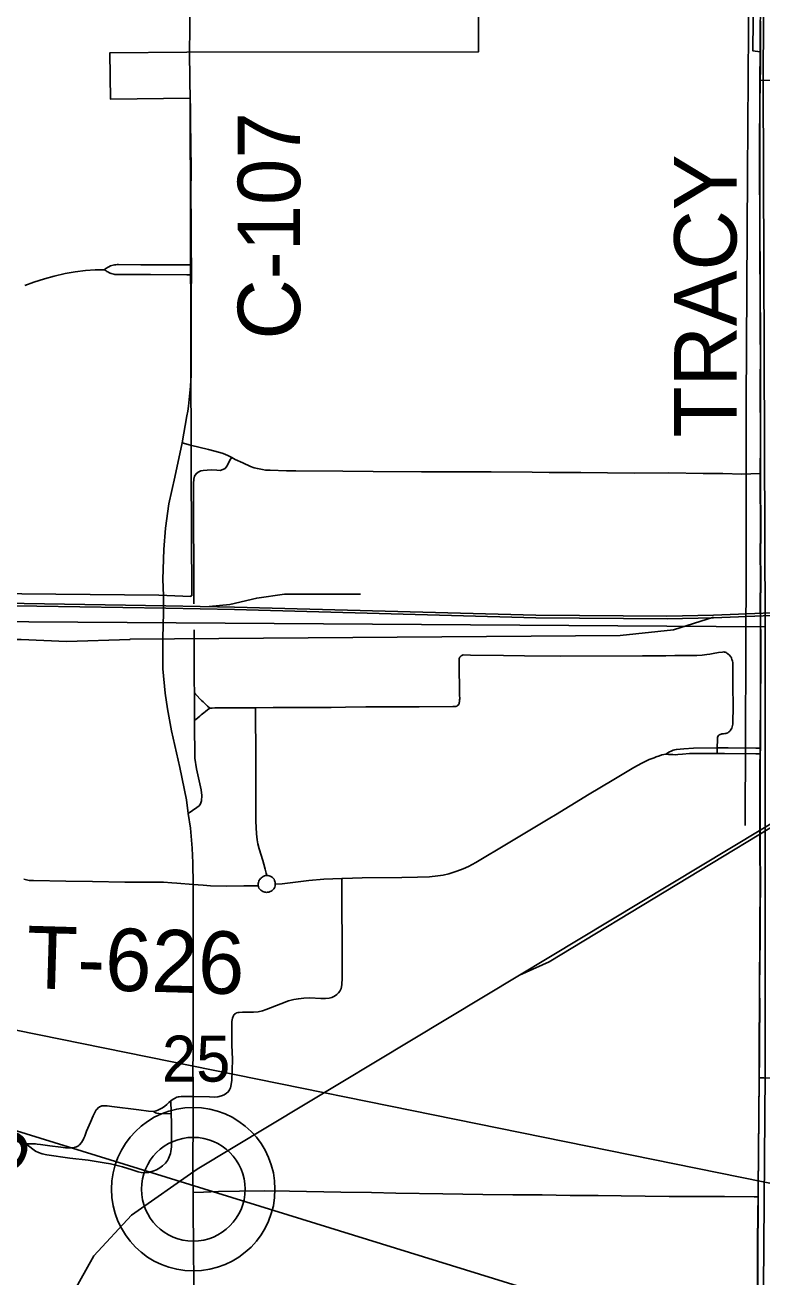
# Model space of a CAD drawing. Extents: x 0 to 34, y 0 to 22.
# Drawn here: x 7.896 to 8.567, y 19.262 to 20.401 of the extents above; entities that cross this region are included whole.
import ezdxf

# ---------------------------------------------------------------- set-up
doc = ezdxf.new("R2010")
doc.units = 0
for name, color, linetype in [('GM_X_City_Street', 7, 'Continuous'), ('GM_X_Corporation', 7, 'Continuous'), ('GM_X_County_Road', 7, 'Continuous'), ('GM_X_County_Road_Text', 7, 'Continuous'), ('GM_X_Minor_River', 7, 'Continuous'), ('GM_X_Rail_Line', 7, 'Continuous'), ('GM_X_Section_Text', 7, 'Continuous'), ('GM_X_Township_Road', 7, 'Continuous'), ('GM_X_Township_Road_Text', 7, 'Continuous'), ('GM_X_Unincorporated', 7, 'Continuous'), ('GM_X_Unincorporated_Location', 7, 'Continuous'), ('SH_Text', 7, 'Continuous')]:
    doc.layers.add(name, color=color, linetype=linetype)

msp = doc.modelspace()

# ---------------------------------------------------------------- linework, layer by layer
at = {"layer": 'GM_X_City_Street'}
for points in [[(7.8957, 20.1645), (7.9039, 20.1675), (7.9134, 20.1706), (7.9224, 20.173), (7.9322, 20.1752), (7.9415, 20.1768), (7.9508, 20.1779), (7.9595, 20.1785), (7.9632, 20.1787), (7.9677, 20.1787)], [(7.9677, 20.1787), (7.9687, 20.1795), (7.9698, 20.1802), (7.9709, 20.1808), (7.9721, 20.1815), (7.9735, 20.1823), (7.9749, 20.1827), (7.9761, 20.183), (7.9772, 20.1832), (7.9783, 20.1833), (7.9795, 20.1834), (7.9809, 20.1834), (8.0012, 20.1833), (8.0229, 20.1833), (8.0392, 20.1833), (8.0428, 20.1833), (8.0472, 20.1833)], [(7.9677, 20.1787), (7.9687, 20.1782), (7.9695, 20.1777), (7.9702, 20.1772), (7.9712, 20.1767), (7.9721, 20.1763), (7.9732, 20.1757), (7.9742, 20.1754), (7.9754, 20.175), (7.9765, 20.1747), (7.9774, 20.1745), (7.9785, 20.1744), (7.9799, 20.1744), (7.9997, 20.1743), (8.0101, 20.1743), (8.0429, 20.1742), (8.0472, 20.1742)]]:
    msp.add_lwpolyline(points, dxfattribs=at)
at = {"layer": 'GM_X_Corporation'}
for points in [[(7.7961, 20.8998), (8.0431, 20.8969), (8.5706, 20.8869), (8.5677, 20.3491), (8.5695, 19.8537), (7.5413, 19.8609), (7.5417, 20.3812), (7.5405, 20.8943)], [(7.5413, 19.8609), (8.5695, 19.8537), (8.5696, 19.4474), (8.5646, 18.8232), (7.5285, 18.8343)]]:
    msp.add_lwpolyline(points, close=True, dxfattribs=at)
for points in [[(8.5605, 20.5722), (8.5584, 20.3778), (8.565, 20.3771), (8.5647, 20.351), (8.9, 20.3511), (8.9, 20.9)], [(7.3931, 19.8888), (8.0175, 19.8825), (8.0468, 19.8814), (8.0468, 19.8821), (8.0475, 19.8821), (8.0471, 19.9967), (8.046, 20.335), (7.9734, 20.3341), (7.9728, 20.376), (8.043, 20.3766), (8.3087, 20.3771), (8.3095, 20.5721)], [(8.5654, 20.4308), (8.565, 20.3824), (8.565, 20.3625), (8.5647, 20.351), (8.5646, 20.3286), (8.5645, 20.2956), (8.5644, 20.2608), (8.5646, 20.2322), (8.5646, 20.2049), (8.5647, 20.1874), (8.5649, 20.1613), (8.5651, 20.1197), (8.5652, 20.1012), (8.5651, 20.0757), (8.5652, 20.0216), (8.5651, 19.9937), (8.5651, 19.9924), (8.5652, 19.9383), (8.565, 19.9215), (8.5653, 19.8985), (8.5651, 19.8718), (8.5652, 19.8606), (8.5653, 19.8435), (8.5654, 19.8267), (8.5652, 19.7782), (8.5651, 19.7596), (8.5649, 19.744), (8.5649, 19.7388), (8.5647, 19.7279), (8.5648, 19.6949), (8.5647, 19.6769), (8.5646, 19.6657), (8.5647, 19.6564), (8.5648, 19.6458), (8.565, 19.6272), (8.5647, 19.5712), (8.5643, 19.5264), (8.5644, 19.5071), (8.5642, 19.481), (8.5641, 19.4624), (8.564, 19.4439), (8.5631, 19.3418), (8.5631, 19.3356), (8.5629, 19.3194), (8.5627, 19.2945), (8.5626, 19.2541)], [(8.5626, 19.2541), (8.5627, 19.2945), (8.5629, 19.3194), (8.5631, 19.3356), (8.5631, 19.3418), (8.564, 19.4439), (8.5641, 19.4624), (8.5642, 19.481), (8.5644, 19.5071), (8.5643, 19.5264), (8.5647, 19.5712), (8.565, 19.6272), (8.5648, 19.6458), (8.5647, 19.6564), (8.5646, 19.6657), (8.5647, 19.6769), (8.5648, 19.6949), (8.5647, 19.7279), (8.5649, 19.7388), (8.5649, 19.744), (8.5651, 19.7596), (8.5652, 19.7782), (8.5654, 19.8267), (8.5653, 19.8435), (8.5652, 19.8606), (8.5651, 19.8718), (8.5653, 19.8985), (8.565, 19.9215), (8.5652, 19.9383), (8.5651, 19.9924), (8.5651, 19.9937), (8.5652, 20.0216), (8.5651, 20.0757), (8.5652, 20.1012), (8.5651, 20.1197), (8.5649, 20.1613), (8.5647, 20.1874), (8.5646, 20.2049), (8.5646, 20.2322), (8.5644, 20.2608), (8.5645, 20.2956), (8.5646, 20.3286), (8.5647, 20.351), (8.565, 20.3625), (8.565, 20.3824), (8.5654, 20.4308)]]:
    msp.add_lwpolyline(points, dxfattribs=at)
at = {"layer": 'GM_X_County_Road'}
for p, q in [((8.0462, 20.3316), (8.0454, 20.3754)), ((8.0472, 20.1742), (8.0472, 20.1833))]:
    msp.add_line(p, q, dxfattribs=at)
for points in [[(8.0454, 20.3754), (8.0458, 20.3992), (8.046, 20.4477), (8.046, 20.4825), (8.0463, 20.5398), (8.0465, 20.5935), (8.0465, 20.6202), (8.0465, 20.6273), (8.0467, 20.6395)], [(8.5649, 20.3505), (8.5652, 20.3619), (8.5652, 20.3818), (8.5654, 20.405)], [(8.5653, 19.9932), (8.5654, 20.021), (8.5653, 20.0751), (8.5654, 20.1006), (8.5653, 20.1191), (8.5651, 20.1608), (8.5649, 20.1869), (8.5648, 20.2043), (8.5648, 20.2317), (8.5647, 20.2603), (8.5648, 20.2951), (8.5648, 20.328), (8.5649, 20.3505)], [(8.0472, 20.1833), (8.0472, 20.1857), (8.047, 20.1938), (8.047, 20.2204), (8.0468, 20.2484), (8.0469, 20.2702), (8.0464, 20.3137), (8.0463, 20.3288), (8.0462, 20.3316)], [(8.0463, 20.0729), (8.0471, 20.0829), (8.0469, 20.0995), (8.0471, 20.1156), (8.0471, 20.1579), (8.0472, 20.1742)], [(8.0388, 20.0211), (8.0431, 20.0457), (8.0439, 20.05), (8.0446, 20.0547), (8.0452, 20.0605), (8.0463, 20.0729)], [(8.0217, 19.8821), (8.0213, 19.8973), (8.022, 19.9243), (8.0236, 19.9437), (8.0268, 19.9656), (8.0321, 19.9899), (8.0388, 20.0211)], [(8.5651, 19.7383), (8.5652, 19.7435), (8.5653, 19.759), (8.5654, 19.7777), (8.5656, 19.8262), (8.5655, 19.843), (8.5654, 19.86), (8.5653, 19.8712), (8.5655, 19.8979), (8.5652, 19.921), (8.5655, 19.9377), (8.5653, 19.9918), (8.5653, 19.9932)], [(8.0444, 19.6839), (8.0426, 19.6963), (8.0366, 19.7258), (8.029, 19.759), (8.0255, 19.7791), (8.0232, 19.7934), (8.0213, 19.8157), (8.0211, 19.8436), (8.0218, 19.8669), (8.0218, 19.8812), (8.0217, 19.8821)], [(8.565, 19.5876), (8.5652, 19.6266), (8.565, 19.6453), (8.5649, 19.6558), (8.5649, 19.6651), (8.565, 19.6763), (8.5651, 19.6944), (8.565, 19.7273), (8.5651, 19.7383)], [(8.0487, 19.6194), (8.0486, 19.6391), (8.0479, 19.6525), (8.0463, 19.6705), (8.0444, 19.6839)], [(8.0488, 19.4265), (8.0488, 19.4301), (8.0487, 19.4381), (8.0486, 19.4504), (8.0487, 19.4663), (8.0488, 19.4878), (8.0488, 19.4895), (8.0488, 19.4953), (8.0488, 19.5278), (8.0488, 19.552), (8.0488, 19.5788), (8.0487, 19.6194)], [(8.5644, 19.4775), (8.5644, 19.4805), (8.5646, 19.5066), (8.5645, 19.5259), (8.5649, 19.5706), (8.565, 19.5876)], [(8.5642, 19.4433), (8.5644, 19.4618), (8.5644, 19.4775)], [(8.5633, 19.335), (8.5633, 19.3412), (8.5642, 19.4433)], [(8.0487, 19.339), (8.0485, 19.3518), (8.0488, 19.4183), (8.0488, 19.4265)], [(8.0487, 19.0766), (8.0487, 19.0828), (8.0489, 19.105), (8.0488, 19.2026), (8.049, 19.2263), (8.0489, 19.2288), (8.0492, 19.2405), (8.0493, 19.2573), (8.049, 19.2883), (8.0488, 19.325), (8.0487, 19.3306), (8.0487, 19.339)], [(8.5621, 19.1128), (8.5618, 19.1454), (8.562, 19.1901), (8.5625, 19.22), (8.5628, 19.2536), (8.5629, 19.294), (8.5631, 19.3188), (8.5633, 19.335)]]:
    msp.add_lwpolyline(points, dxfattribs=at)
at = {"layer": 'GM_X_Minor_River'}
msp.add_lwpolyline([(8.5556, 20.857), (8.5541, 20.7765), (8.554, 20.6532), (8.5547, 20.441), (8.5535, 20.2661), (8.5523, 20.057), (8.5522, 19.9109), (8.5514, 19.673)], dxfattribs=at)
at = {"layer": 'GM_X_Rail_Line'}
for points in [[(6.9125, 19.8919), (7.7104, 19.8779), (8.0238, 19.873), (8.0864, 19.8717), (8.3608, 19.8644), (8.4801, 19.8635), (8.5225, 19.8644), (8.5752, 19.8664), (8.6397, 19.8712), (8.6895, 19.8758), (8.7741, 19.8862), (8.8479, 19.894), (8.8982, 19.8986), (8.9, 19.8988)], [(6.9125, 19.8896), (7.7104, 19.8755), (8.0238, 19.8707), (8.0863, 19.8694), (8.3608, 19.862), (8.4802, 19.8611), (8.5226, 19.862), (8.5753, 19.8641), (8.6399, 19.8689), (8.6898, 19.8735), (8.7744, 19.8839), (8.8481, 19.8917), (8.8984, 19.8963), (8.9, 19.8965)], [(8.3458, 19.5368), (8.6204, 19.7022), (8.6886, 19.7422), (8.7029, 19.7509), (8.7177, 19.7607), (8.7265, 19.7674), (8.735, 19.7742), (8.7726, 19.8102), (8.7996, 19.8361), (8.811, 19.8463), (8.8251, 19.8577), (8.8403, 19.8675), (8.8538, 19.8752), (8.8697, 19.8821), (8.8909, 19.8894), (8.9, 19.8916)], [(8.0633, 19.8722), (8.0823, 19.8741), (8.1067, 19.88), (8.1319, 19.8835), (8.2012, 19.8835)], [(7.9911, 19.8427), (8.4375, 19.8458), (8.4861, 19.8511), (8.5224, 19.8626)], [(7.1918, 18.2168), (7.1976, 18.2415), (7.1985, 18.2668), (7.1971, 18.288), (7.1907, 18.3043), (7.1721, 18.3357), (7.1648, 18.3522), (7.1593, 18.374), (7.1584, 18.3906), (7.1596, 18.4069), (7.163, 18.42), (7.1898, 18.4877), (7.3035, 18.7703), (7.7161, 19.7423), (7.7367, 19.7856), (7.7522, 19.8033), (7.7707, 19.8183), (7.7881, 19.8278), (7.8054, 19.8353), (7.8226, 19.8392), (7.8515, 19.8421), (7.8923, 19.8423), (7.9335, 19.8404), (7.9913, 19.8421)], [(8.3458, 19.5368), (8.3728, 19.5489), (8.6055, 19.6898), (8.6362, 19.7063), (8.6465, 19.7115), (8.6699, 19.7211), (8.6883, 19.727), (8.7032, 19.7308), (8.7225, 19.7356), (8.7421, 19.7392), (8.759, 19.7414), (8.7728, 19.7425), (8.8019, 19.7436), (8.8224, 19.7433)], [(5.7724, 14.1), (5.9023, 14.4065), (6.108, 14.9012), (7.0925, 17.2371), (7.3462, 17.8422), (7.5826, 18.397), (7.8741, 19.1084), (7.9022, 19.1708), (7.9338, 19.2375), (7.9584, 19.2815), (7.9927, 19.3184), (8.0524, 19.3602), (8.3458, 19.5368)]]:
    msp.add_lwpolyline(points, dxfattribs=at)
at = {"layer": 'GM_X_Township_Road'}
for p, q in [((8.0388, 20.0211), (8.0464, 20.0192)), ((8.0499, 19.7682), (8.0499, 19.7936))]:
    msp.add_line(p, q, dxfattribs=at)
for points in [[(8.0464, 20.0192), (8.0628, 20.0152), (8.0732, 20.0125), (8.076, 20.0116), (8.0805, 20.0096), (8.0839, 20.0079)], [(8.0495, 19.8747), (8.0491, 19.9843), (8.0495, 19.9881), (8.0501, 19.9909), (8.0515, 19.9931), (8.0535, 19.9946), (8.0558, 19.9956), (8.058, 19.9961), (8.0615, 19.9964), (8.0658, 19.9966), (8.0705, 19.9963), (8.0735, 19.9961), (8.0758, 19.9968), (8.0778, 19.9979), (8.0794, 20.0001), (8.0829, 20.0063), (8.0839, 20.0079)], [(8.0839, 20.0079), (8.0871, 20.0062), (8.094, 20.0029), (8.101, 19.9998), (8.1043, 19.9986), (8.1073, 19.9978), (8.112, 19.9968), (8.1147, 19.9964), (8.119, 19.9962), (8.1337, 19.9958), (8.1423, 19.9957), (8.1852, 19.9955), (8.2126, 19.9952), (8.2567, 19.9949), (8.2965, 19.9949), (8.3202, 19.9947), (8.3575, 19.9945), (8.373, 19.9942), (8.3842, 19.9943), (8.4017, 19.9942), (8.4502, 19.9937), (8.4818, 19.9938), (8.513, 19.9934), (8.5309, 19.9932), (8.5484, 19.9928), (8.5565, 19.993), (8.5653, 19.9932)], [(8.0499, 19.7936), (8.0498, 19.8046), (8.0496, 19.8511)], [(8.1056, 19.7801), (8.1215, 19.7803), (8.1588, 19.7805), (8.1743, 19.7805), (8.1874, 19.7806), (8.2061, 19.781), (8.2291, 19.7811), (8.2546, 19.7811), (8.2851, 19.7813), (8.2879, 19.7814), (8.2889, 19.7817), (8.2895, 19.7821), (8.29, 19.7826), (8.2906, 19.7833), (8.2909, 19.784), (8.2911, 19.7848), (8.2913, 19.7855), (8.2913, 19.7863), (8.2914, 19.7873), (8.2915, 19.7882), (8.2914, 19.7918), (8.2912, 19.7998), (8.291, 19.8134), (8.291, 19.8234), (8.291, 19.8242), (8.2911, 19.825), (8.2914, 19.8257), (8.2917, 19.8263), (8.2922, 19.8269), (8.2928, 19.8274), (8.2933, 19.8278), (8.2939, 19.828), (8.2947, 19.8282), (8.3012, 19.8281), (8.3312, 19.8277), (8.3504, 19.8273), (8.3834, 19.8272), (8.458, 19.8273), (8.4792, 19.8275), (8.4873, 19.8276), (8.4917, 19.8276), (8.5072, 19.8276), (8.5121, 19.8279), (8.5163, 19.8285), (8.5192, 19.829), (8.5221, 19.8295), (8.5272, 19.8304), (8.5307, 19.8308), (8.5318, 19.8309), (8.5325, 19.8308), (8.5331, 19.8306), (8.5341, 19.8303), (8.5347, 19.8298), (8.5355, 19.8292), (8.5371, 19.8279)], [(8.5258, 19.7436), (8.526, 19.7514), (8.5261, 19.7523), (8.5262, 19.753), (8.5266, 19.7541), (8.5271, 19.7549), (8.5277, 19.7555), (8.5285, 19.7559), (8.5295, 19.7562), (8.5302, 19.7563), (8.531, 19.7564), (8.5317, 19.7565), (8.5327, 19.7567), (8.5337, 19.7568), (8.5345, 19.757), (8.5355, 19.7574), (8.5366, 19.7581), (8.5372, 19.7586), (8.5376, 19.7591), (8.5381, 19.7596), (8.5387, 19.7606), (8.5393, 19.7617), (8.5396, 19.7627), (8.5398, 19.7639), (8.54, 19.7653), (8.5401, 19.7685), (8.5404, 19.7791), (8.54, 19.8022), (8.5402, 19.814), (8.5402, 19.8197), (8.5401, 19.8212), (8.5398, 19.8224), (8.5396, 19.8234), (8.5393, 19.8242), (8.539, 19.8253), (8.5385, 19.8261), (8.538, 19.8269), (8.5371, 19.8279)], [(8.0499, 19.7936), (8.0509, 19.7925), (8.0565, 19.7868), (8.0578, 19.7854), (8.0598, 19.7837), (8.0619, 19.7817), (8.0641, 19.7797)], [(8.0499, 19.7682), (8.0513, 19.7694), (8.0549, 19.7726), (8.0562, 19.7736), (8.0584, 19.7754), (8.0601, 19.7768), (8.0619, 19.7781), (8.0641, 19.7797)], [(8.0641, 19.7797), (8.0662, 19.7799), (8.0684, 19.7801), (8.0725, 19.7801), (8.0779, 19.7801), (8.1003, 19.78), (8.1056, 19.7801)], [(8.1159, 19.6274), (8.1154, 19.6297), (8.1145, 19.6331), (8.1132, 19.6379), (8.1123, 19.6412), (8.109, 19.6519), (8.1078, 19.6562), (8.1071, 19.6599), (8.1065, 19.6655), (8.106, 19.6768), (8.1058, 19.6942), (8.106, 19.7283), (8.1059, 19.7507), (8.1057, 19.7625), (8.1056, 19.7772), (8.1056, 19.7801)], [(8.0444, 19.6839), (8.0521, 19.6894), (8.0542, 19.6909), (8.0554, 19.6927), (8.0565, 19.6955), (8.0566, 19.7002), (8.056, 19.7055), (8.0536, 19.7163), (8.0518, 19.7246), (8.0503, 19.7343), (8.0502, 19.7385), (8.0499, 19.7618), (8.0499, 19.7682)], [(8.4791, 19.7379), (8.481, 19.7392), (8.4823, 19.7399), (8.4839, 19.7407), (8.4857, 19.7414), (8.4873, 19.7419), (8.4888, 19.7422), (8.4923, 19.7426), (8.4956, 19.7429), (8.5043, 19.7434), (8.5258, 19.7436)], [(8.5256, 19.7385), (8.5257, 19.7396), (8.5258, 19.7428), (8.5258, 19.7436)], [(8.5258, 19.7436), (8.536, 19.7437), (8.5609, 19.7435), (8.5652, 19.7435)], [(8.3735, 19.6797), (8.3786, 19.6828), (8.392, 19.6908), (8.4094, 19.7016), (8.4304, 19.7138), (8.45, 19.7258), (8.4572, 19.7297), (8.464, 19.7329), (8.4685, 19.7346), (8.4704, 19.7354), (8.4732, 19.7365), (8.4754, 19.7372), (8.4791, 19.7379)], [(8.4791, 19.7379), (8.4815, 19.7377), (8.4828, 19.7376), (8.4837, 19.7376), (8.4855, 19.7375), (8.4877, 19.7374), (8.4899, 19.7376), (8.4943, 19.738), (8.5007, 19.7385), (8.5125, 19.7386), (8.5256, 19.7385)], [(8.5256, 19.7385), (8.5324, 19.7384), (8.5611, 19.7383), (8.5651, 19.7383)], [(8.1842, 19.6249), (8.1852, 19.6249), (8.2026, 19.6254), (8.2387, 19.6258), (8.253, 19.6259), (8.2641, 19.6264), (8.2715, 19.6271), (8.2764, 19.6278), (8.2817, 19.6291), (8.2888, 19.6313), (8.2946, 19.6335), (8.2996, 19.6358), (8.3061, 19.6394), (8.3355, 19.6568), (8.3735, 19.6797)], [(7.8947, 19.624), (7.8972, 19.6234), (7.8996, 19.623), (7.9033, 19.6229), (7.9329, 19.6224), (7.9573, 19.622), (7.9865, 19.6215), (8.0217, 19.6213), (8.0294, 19.6209), (8.0339, 19.6206), (8.0487, 19.6194)], [(8.0487, 19.6194), (8.058, 19.6187), (8.0646, 19.6182), (8.0788, 19.6178), (8.0949, 19.6181), (8.1026, 19.618), (8.1081, 19.6181)], [(8.0488, 19.4265), (8.0637, 19.426), (8.0681, 19.4258), (8.0713, 19.4261), (8.0745, 19.4269), (8.0769, 19.4279), (8.0792, 19.4293), (8.0807, 19.4306), (8.0819, 19.4323), (8.0827, 19.4342), (8.0835, 19.4374), (8.084, 19.4411), (8.0844, 19.4499), (8.0845, 19.4605), (8.084, 19.473), (8.084, 19.4898), (8.0841, 19.4947), (8.0846, 19.4976), (8.0849, 19.4987), (8.0854, 19.4997), (8.0859, 19.5006), (8.0865, 19.5012), (8.087, 19.5017), (8.0878, 19.5022), (8.0884, 19.5025), (8.0896, 19.5028), (8.0906, 19.5029), (8.0936, 19.5032), (8.0992, 19.5031), (8.1036, 19.5031), (8.108, 19.5035), (8.1118, 19.5043), (8.1154, 19.5054), (8.1287, 19.5107), (8.1357, 19.5133), (8.1404, 19.5146), (8.1446, 19.5154), (8.1495, 19.5159), (8.155, 19.5162), (8.1649, 19.5157), (8.1694, 19.5156), (8.1726, 19.516), (8.1751, 19.5166), (8.1776, 19.5177), (8.1797, 19.5192), (8.1811, 19.5206), (8.1823, 19.5223), (8.1834, 19.5247), (8.184, 19.5279), (8.1843, 19.5344), (8.1844, 19.5549), (8.1843, 19.5702), (8.184, 19.596), (8.1842, 19.6115), (8.1842, 19.6234), (8.1842, 19.6249)], [(8.1081, 19.6181), (8.1081, 19.6193), (8.1081, 19.6203), (8.1082, 19.6211), (8.1086, 19.6224), (8.1089, 19.6232), (8.1094, 19.6239), (8.1102, 19.6248), (8.1109, 19.6255), (8.1116, 19.6261), (8.1124, 19.6266), (8.1131, 19.627), (8.1137, 19.6272), (8.1146, 19.6274), (8.1159, 19.6274)], [(8.1081, 19.6181), (8.1082, 19.6172), (8.1086, 19.616), (8.1094, 19.6151), (8.1105, 19.6141), (8.1113, 19.6135), (8.1122, 19.613), (8.1131, 19.6126), (8.114, 19.6123), (8.1147, 19.6122), (8.1155, 19.6121), (8.1165, 19.6122), (8.1178, 19.6124), (8.1189, 19.6128), (8.1199, 19.6132), (8.1207, 19.6138), (8.1216, 19.6146), (8.1223, 19.6155), (8.1229, 19.6163), (8.1232, 19.6169), (8.1235, 19.6182), (8.1236, 19.6197)], [(8.1159, 19.6274), (8.1169, 19.6275), (8.1179, 19.6273), (8.1189, 19.627), (8.1196, 19.6267), (8.1202, 19.6263), (8.121, 19.6257), (8.1218, 19.6248), (8.1224, 19.6242), (8.123, 19.623), (8.1233, 19.6221), (8.1235, 19.6213), (8.1236, 19.6197)], [(8.1236, 19.6197), (8.1297, 19.62), (8.1541, 19.6229), (8.1678, 19.624), (8.1842, 19.6249)], [(8.5633, 19.335), (8.5633, 19.3412), (8.5642, 19.4433)], [(8.5642, 19.4433), (8.5684, 19.4433), (8.5792, 19.4431), (8.5898, 19.443), (8.6242, 19.4424), (8.6699, 19.4415), (8.6867, 19.4413), (8.7234, 19.441), (8.7576, 19.4404), (8.7725, 19.4402), (8.8123, 19.4394), (8.8638, 19.4388), (8.8918, 19.4384), (8.9, 19.4384)], [(8.0286, 19.4224), (8.0306, 19.4238), (8.0312, 19.4243), (8.0323, 19.4249), (8.0332, 19.4254), (8.034, 19.4257), (8.0351, 19.426), (8.0362, 19.4262), (8.0378, 19.4263), (8.0409, 19.4264), (8.0488, 19.4265)], [(7.8073, 19.417), (7.826, 19.4094), (7.8588, 19.396), (7.8668, 19.3927), (7.8726, 19.3906), (7.8755, 19.3896), (7.8793, 19.3884), (7.8908, 19.3849), (7.8944, 19.3839), (7.8968, 19.3833)], [(7.8968, 19.3833), (7.9007, 19.3834), (7.9038, 19.3832), (7.9053, 19.3832), (7.9069, 19.383), (7.9097, 19.3827), (7.9118, 19.3824), (7.9184, 19.3815), (7.9283, 19.3802), (7.9327, 19.3797), (7.9347, 19.3796), (7.9362, 19.3796), (7.9378, 19.3796), (7.939, 19.3797), (7.94, 19.3798), (7.9415, 19.3802), (7.9426, 19.3806), (7.9438, 19.3811), (7.9446, 19.3818), (7.9454, 19.3825), (7.9472, 19.3846), (7.9481, 19.3861), (7.9489, 19.3875), (7.9494, 19.3886), (7.9501, 19.3903), (7.9518, 19.3948), (7.9554, 19.403), (7.9578, 19.4089), (7.9592, 19.4119), (7.9599, 19.4131), (7.9605, 19.4141), (7.9613, 19.415), (7.962, 19.4158), (7.9634, 19.4169), (7.9645, 19.4174), (7.9657, 19.4178), (7.9669, 19.4179), (7.9686, 19.418), (7.9706, 19.4179), (7.9749, 19.4174), (7.9994, 19.4143), (8.0082, 19.4131), (8.0127, 19.4127)], [(8.0127, 19.4127), (8.0152, 19.4134), (8.0166, 19.414), (8.0185, 19.4148), (8.0203, 19.4159), (8.0219, 19.4168), (8.023, 19.4177), (8.0247, 19.4192), (8.0267, 19.4208), (8.0286, 19.4224)], [(8.0287, 19.4105), (8.0287, 19.4117), (8.0286, 19.4224)], [(7.8968, 19.3833), (7.8975, 19.3826), (7.9028, 19.3783), (7.9053, 19.3767), (7.908, 19.3754), (7.9114, 19.3742), (7.9156, 19.3733), (7.9365, 19.3704), (7.9531, 19.3683), (7.9679, 19.3659), (7.9734, 19.365), (7.9783, 19.3639), (7.9844, 19.3623), (7.9933, 19.3595), (7.9986, 19.3578), (8.0015, 19.3571), (8.0045, 19.3569), (8.0061, 19.3571), (8.008, 19.3573), (8.0096, 19.3577), (8.012, 19.3584), (8.0154, 19.3597), (8.0186, 19.3615), (8.021, 19.3632), (8.0236, 19.3657), (8.0254, 19.3681), (8.0265, 19.3701), (8.0277, 19.3729), (8.0282, 19.3746), (8.0286, 19.3763), (8.029, 19.3805), (8.0291, 19.3873), (8.029, 19.4023), (8.0287, 19.4105)], [(8.0127, 19.4127), (8.0144, 19.4116), (8.0156, 19.4112), (8.0177, 19.4109), (8.0287, 19.4105)], [(8.0487, 19.339), (8.0581, 19.3393), (8.0718, 19.3399), (8.091, 19.3403), (8.1134, 19.3404), (8.1365, 19.3401), (8.1831, 19.3394), (8.2111, 19.339), (8.2334, 19.3383), (8.2762, 19.3377), (8.3124, 19.3372), (8.3397, 19.337), (8.3665, 19.3368), (8.3919, 19.3364), (8.4174, 19.3362), (8.4385, 19.3359), (8.4821, 19.3355), (8.5032, 19.3353), (8.5324, 19.3353), (8.5595, 19.335), (8.5633, 19.335)]]:
    msp.add_lwpolyline(points, dxfattribs=at)
at = {"layer": 'GM_X_Unincorporated'}
for radius in [0.0744, 0.0472]:
    msp.add_circle((8.0489, 19.342), radius, dxfattribs=at)
at = {"layer": 'GM_X_Unincorporated_Location'}
msp.add_line((8.0489, 19.342), (8.0489, 19.342), dxfattribs=at)
at = {"layer": 'SH_Text'}
msp.add_lwpolyline([(7.0279, 19.6612), (9.327, 18.9498), (9.327, 19.1946)], close=True, dxfattribs=at)

# ---------------------------------------------------------------- texts
at = {"layer": 'GM_X_County_Road_Text'}
for s, p in [('C-107', (8.1462, 20.1152)), ('TRACY', (8.5435, 20.0261))]:
    msp.add_text(s, height=0.05682, rotation=90, dxfattribs=at).set_placement(p)
at = {"layer": 'GM_X_Section_Text'}
msp.add_text('25', height=0.04186, rotation=0, dxfattribs=at).set_placement((8.0204, 19.4399))
at = {"layer": 'GM_X_Township_Road_Text'}
for s, rotation, p in [('T-626', 358.3515, (7.8963, 19.525)), ('T-628', 67.2738, (7.8267, 19.2079))]:
    msp.add_text(s, height=0.05682, rotation=rotation, dxfattribs=at).set_placement(p)

doc.saveas('drawing.dxf')
